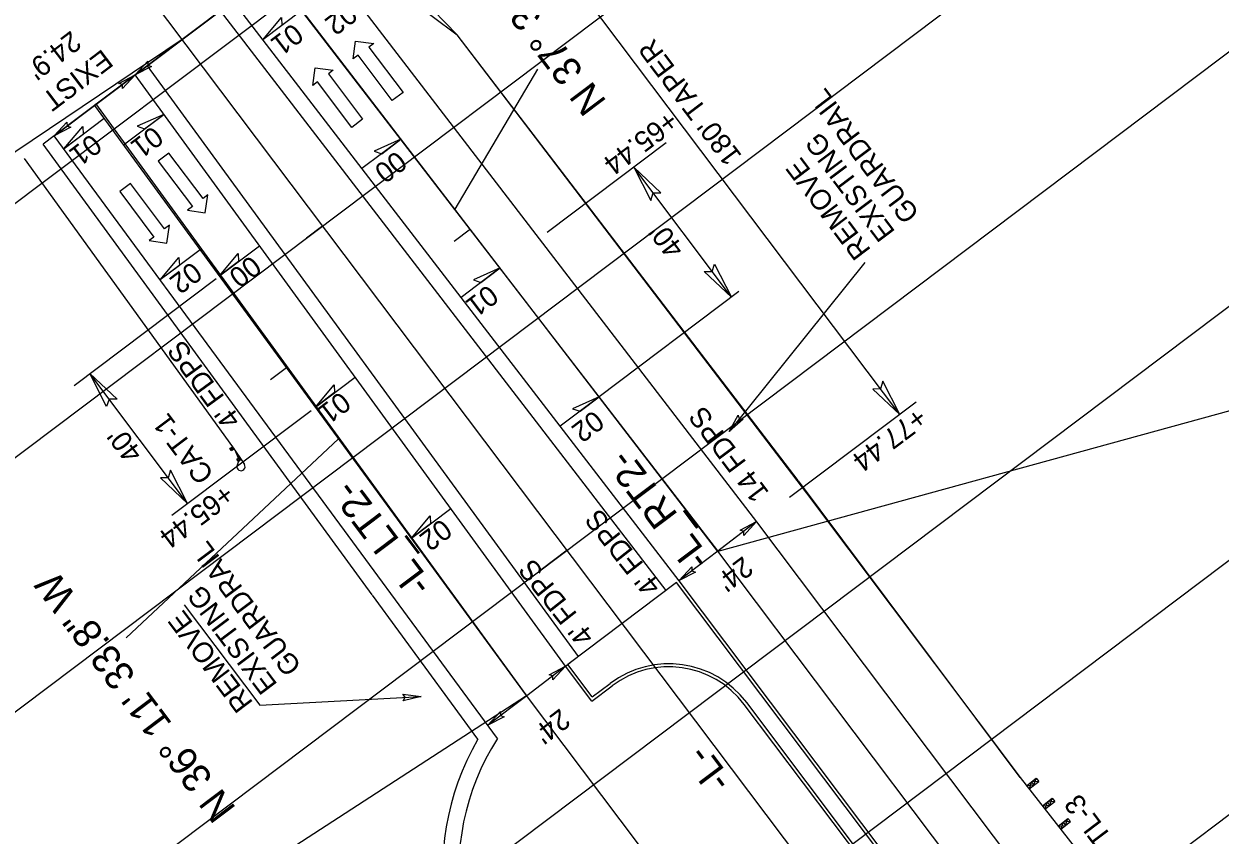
# Model space of a CAD drawing. Extents: x 1262309 to 1264352, y 775189 to 777755.
# Drawn here: x 1262668.6 to 1262963, y 777260.9 to 777460.6 of the extents above; entities that cross this region are included whole.
import ezdxf

# ---------------------------------------------------------------- set-up
doc = ezdxf.new("R2010")
doc.units = 0
for name, color, linetype in [('Default', 7, 'Continuous'), ('Prop Conc 5in Monolithic Keyed In Island', 7, 'Continuous'), ('Prop Dimension', 7, 'Continuous'), ('Prop Dimension Text', 7, 'Continuous'), ('Prop EOT', 7, 'Continuous'), ('Prop GRAU CAT1 Cell', 7, 'Continuous'), ('Prop Guardrail', 7, 'Continuous'), ('Prop Guardrail Anchor Unit CELL', 7, 'Continuous'), ('Prop Horizontal Alignment', 7, 'Continuous'), ('Prop Horizontal Alignment Station Label', 7, 'Continuous'), ('Prop Horizontal Alignment Tick Large', 7, 'Continuous'), ('Prop Horizontal Alignment Tick Small', 7, 'Continuous'), ('Prop Lane Arrow CELL', 7, 'Continuous'), ('Prop Lane Lines', 7, 'Continuous'), ('Prop Paved Shoulder', 7, 'Continuous'), ('Prop Superelevation  Arrow CELL', 7, 'Continuous'), ('Prop Superelevation Label', 7, 'Continuous'), ('Prop Terminator CELL', 7, 'Continuous'), ('Scratch_Level_3', 7, 'Continuous')]:
    doc.layers.add(name, color=color, linetype=linetype)

msp = doc.modelspace()

# ---------------------------------------------------------------- linework, layer by layer
at = {"layer": 'Default'}
for p, q in [((1262742.12, 777410.88), (1262742.12, 777410.88)), ((1262742.12, 777410.88), (1262742.12, 777410.88)), ((1262802.29, 777331), (1262802.29, 777331)), ((1262802.29, 777331), (1262802.29, 777331))]:
    msp.add_line(p, q, dxfattribs=at)
at = {"layer": 'Prop Conc 5in Monolithic Keyed In Island'}
for p, q in [((1262829.24, 777323.06), (1262802.48, 777302.91)), ((1262891.25, 777240.73), (1262829.24, 777323.06)), ((1262808.49, 777294.92), (1262802.48, 777302.91)), ((1262808.49, 777294.92), (1262812.89, 777298.23)), ((1262888.06, 777238.32), (1262846.5, 777293.5))]:
    msp.add_line(p, q, dxfattribs=at)
msp.add_arc((1262827.33, 777279.06), 24, 36.9874, 126.9874, dxfattribs=at)
at = {"layer": 'Prop Dimension'}
for p, q in [((1262842.76, 777393.34), (1262818.69, 777425.29)), ((1262680.93, 777371.6), (1262715.9, 777397.94)), ((1262844.57, 777394.7), (1262810.17, 777368.79)), ((1262708.83, 777342.54), (1262684.76, 777374.49)), ((1262705, 777339.65), (1262739.25, 777365.45))]:
    msp.add_line(p, q, dxfattribs=at)
for points in [[(1262699.99, 777450.12), (1262695.94, 777448.01), (1262699.06, 777451.38), (1262699.09, 777450.4)], [(1262691.93, 777445.92), (1262695.98, 777448.03), (1262692.87, 777444.65), (1262692.84, 777445.64)], [(1262680.1, 777435.13), (1262676.05, 777433.02), (1262679.16, 777436.4), (1262679.19, 777435.41)]]:
    msp.add_lwpolyline(points, close=True, dxfattribs=at)
at = {"layer": 'Prop Dimension Text'}
for p, q in [((1262884.16, 777364.43), (1262775.74, 777508.38)), ((1262720.06, 777466.17), (1262695.95, 777448.02)), ((1262695.94, 777448.01), (1262676.05, 777433.02)), ((1262695.94, 777448.01), (1262676.05, 777433.02)), ((1262826.65, 777431.28), (1262797.38, 777409.24)), ((1262888.21, 777367.48), (1262857, 777343.97)), ((1262848.94, 777338.05), (1262839.04, 777330.52)), ((1262848.94, 777338.05), (1262839.39, 777330.78)), ((1262839.39, 777330.78), (1262829.83, 777323.52)), ((1262708, 777317.57), (1262726.64, 777292.83)), ((1262801.88, 777302.46), (1262792.33, 777295.19)), ((1262792.33, 777295.19), (1262782.78, 777287.93))]:
    msp.add_line(p, q, dxfattribs=at)
for points in [[(1262825.34, 777419.03), (1262818.69, 777425.29), (1262822.86, 777417.1), (1262823.44, 777418.98)], [(1262838.58, 777401.46), (1262842.76, 777393.34), (1262836.03, 777399.6), (1262838, 777399.65)], [(1262688.94, 777366.37), (1262684.76, 777374.49), (1262691.49, 777368.22), (1262689.52, 777368.18)], [(1262877.51, 777370.68), (1262884.16, 777364.43), (1262879.99, 777372.62), (1262879.41, 777370.74)], [(1262702.18, 777348.8), (1262708.83, 777342.54), (1262704.66, 777350.73), (1262704.08, 777348.85)], [(1262844.89, 777335.94), (1262848.94, 777338.05), (1262845.82, 777334.67), (1262845.79, 777335.65)], [(1262844.89, 777335.94), (1262848.94, 777338.05), (1262845.82, 777334.67), (1262845.79, 777335.65)], [(1262833.89, 777325.62), (1262829.83, 777323.52), (1262832.95, 777326.89), (1262832.98, 777325.91)], [(1262797.83, 777300.35), (1262801.88, 777302.46), (1262798.76, 777299.08), (1262798.74, 777300.06)], [(1262786.83, 777290.03), (1262782.78, 777287.93), (1262785.89, 777291.3), (1262785.92, 777290.32)]]:
    msp.add_lwpolyline(points, close=True, dxfattribs=at)
for points in [[(1262875.6, 777401.82), (1262842.2, 777360.23)], [(1262726.64, 777292.83), (1262766.38, 777295.04)]]:
    msp.add_lwpolyline(points, dxfattribs=at)
at = {"layer": 'Prop EOT'}
for p, q in [((1262676.05, 777433.02), (1262739.39, 777480.73)), ((1262848.98, 777337.98), (1262739.39, 777480.73)), ((1262695.94, 777448.01), (1262720.06, 777466.17)), ((1262829.84, 777323.51), (1262720.06, 777466.17)), ((1262801.88, 777302.46), (1262695.94, 777448.01)), ((1262785.15, 777284.66), (1262676.05, 777433.02)), ((1262808.35, 777293.87), (1262801.88, 777302.46)), ((1262808.35, 777293.87), (1262813.34, 777297.63)), ((1262887.46, 777237.86), (1262845.9, 777293.05))]:
    msp.add_line(p, q, dxfattribs=at)
for points in [[(1262965.52, 777183.26), (1262848.98, 777337.98)], [(1262891.85, 777241.18), (1262829.84, 777323.51)]]:
    msp.add_lwpolyline(points, dxfattribs=at)
for centre, radius, start, end in [((1262827.33, 777279.06), 23.25, 36.9874, 126.9874), ((1262835.62, 777252.21), 60, 147.262, 230.9826)]:
    msp.add_arc(centre, radius, start, end, dxfattribs=at)
at = {"layer": 'Prop GRAU CAT1 Cell'}
for p, q in [((1262719.23, 777356.05), (1262719.9, 777356.5)), ((1262719.62, 777355.47), (1262719.23, 777356.05)), ((1262720.29, 777355.92), (1262719.23, 777356.05)), ((1262719.9, 777356.5), (1262719.62, 777355.47)), ((1262720.29, 777355.92), (1262719.62, 777355.47)), ((1262719.9, 777356.5), (1262721.88, 777353.56)), ((1262719.9, 777356.5), (1262720.29, 777355.92)), ((1262721.5, 777353.41), (1262720.77, 777355.21)), ((1262720.97, 777353.47), (1262721.64, 777353.92)), ((1262721.36, 777352.89), (1262720.97, 777353.47)), ((1262722.03, 777353.34), (1262720.97, 777353.47)), ((1262721.08, 777351.91), (1262721.44, 777352.95)), ((1262721.64, 777353.92), (1262721.36, 777352.89)), ((1262722.03, 777353.34), (1262721.36, 777352.89)), ((1262721.64, 777353.92), (1262722.03, 777353.34)), ((1262721.95, 777353.45), (1262721.88, 777353.56)), ((1262721.88, 777353.56), (1262722.84, 777352.14))]:
    msp.add_line(p, q, dxfattribs=at)
msp.add_ellipse((1262722.01, 777351.58), major_axis=(0.824, 0.555), ratio=0.995379, start_param=2.210226, end_param=6.283185, dxfattribs=at)
at = {"layer": 'Prop Guardrail'}
for p, q in [((1262775.22, 777457.9), (1262747.34, 777486.63)), ((1262859.18, 777348.14), (1262775.22, 777457.9)), ((1262668.63, 777427.42), (1262719.9, 777356.5)), ((1262913.85, 777275.05), (1262859.21, 777348.11))]:
    msp.add_line(p, q, dxfattribs=at)
at = {"layer": 'Prop Guardrail Anchor Unit CELL'}
for p, q in [((1262913.83, 777275.03), (1262942.69, 777238.26)), ((1262915.4, 777273.03), (1262917.76, 777274.88)), ((1262916.01, 777272.24), (1262918.37, 777274.1)), ((1262916.58, 777273.96), (1262916.01, 777272.24)), ((1262918.37, 777274.1), (1262916.58, 777273.96)), ((1262916.58, 777273.96), (1262917.19, 777273.17)), ((1262917.19, 777273.17), (1262917.76, 777274.88)), ((1262917.76, 777274.88), (1262918.37, 777274.1)), ((1262917.19, 777273.17), (1262915.4, 777273.03)), ((1262915.4, 777273.03), (1262916.01, 777272.24)), ((1262916.01, 777272.24), (1262917.19, 777273.17)), ((1262919.29, 777268.08), (1262921.69, 777269.96)), ((1262919.29, 777268.08), (1262921.11, 777268.23)), ((1262919.9, 777267.29), (1262922.31, 777269.17)), ((1262920.49, 777269.02), (1262919.9, 777267.29)), ((1262922.31, 777269.17), (1262920.49, 777269.02)), ((1262920.49, 777269.02), (1262921.11, 777268.23)), ((1262921.11, 777268.23), (1262921.69, 777269.96)), ((1262921.69, 777269.96), (1262922.31, 777269.17)), ((1262923.18, 777263.12), (1262925.57, 777265)), ((1262924.99, 777263.27), (1262925.57, 777265)), ((1262925.57, 777265), (1262926.19, 777264.21)), ((1262923.18, 777263.12), (1262924.99, 777263.27)), ((1262923.8, 777262.33), (1262926.19, 777264.21)), ((1262924.38, 777264.06), (1262923.8, 777262.33)), ((1262926.19, 777264.21), (1262924.38, 777264.06)), ((1262924.38, 777264.06), (1262924.99, 777263.27))]:
    msp.add_line(p, q, dxfattribs=at)
at = {"layer": 'Prop Horizontal Alignment'}
for p, q in [((1263127.22, 776899.61), (1262639.84, 777546.67)), ((1262839.42, 777330.73), (1262729.72, 777473.45)), ((1262839.42, 777330.73), (1262729.72, 777473.45)), ((1262792.29, 777295.24), (1262685.99, 777440.52)), ((1262792.29, 777295.24), (1262685.99, 777440.52)), ((1262792.29, 777295.24), (1262685.99, 777440.52)), ((1262792.29, 777295.24), (1262685.99, 777440.52))]:
    msp.add_line(p, q, dxfattribs=at)
at = {"layer": 'Prop Horizontal Alignment Station Label'}
for p, q in [((1262795.02, 777449.4), (1262774.64, 777414.98)), ((1262992.51, 777372.78), (1262839.42, 777330.73)), ((1262693.74, 777309.43), (1262746.03, 777358.47)), ((1262632.6, 777191.78), (1262792.29, 777295.24))]:
    msp.add_line(p, q, dxfattribs=at)
msp.add_lwpolyline([(1262707.56, 777456.76), (1262417.03, 777261.18), (1262308.75, 777404.89)], dxfattribs=at)
at = {"layer": 'Prop Horizontal Alignment Tick Large'}
msp.add_line((1262802.29, 777331), (1262795.9, 777326.19), dxfattribs=at)
at = {"layer": 'Prop Horizontal Alignment Tick Small'}
for p, q in [((1262742.12, 777410.88), (1262738.13, 777407.87)), ((1262778.48, 777410.02), (1262774.49, 777407.01)), ((1262733.24, 777375.94), (1262729.25, 777372.93))]:
    msp.add_line(p, q, dxfattribs=at)
at = {"layer": 'Prop Lane Arrow CELL'}
for p, q in [((1262749.63, 777451.99), (1262750.22, 777456.37)), ((1262750.22, 777456.37), (1262754.67, 777455.78)), ((1262754.67, 777455.78), (1262753.47, 777454.88)), ((1262753.47, 777454.88), (1262761.89, 777443.7)), ((1262750.83, 777452.89), (1262749.63, 777451.99)), ((1262759.26, 777441.71), (1262750.83, 777452.89)), ((1262739.67, 777445.39), (1262740.25, 777449.77)), ((1262740.25, 777449.77), (1262744.71, 777449.18)), ((1262744.71, 777449.18), (1262743.51, 777448.28)), ((1262743.51, 777448.28), (1262751.93, 777437.1)), ((1262740.87, 777446.3), (1262739.67, 777445.39)), ((1262749.29, 777435.11), (1262740.87, 777446.3)), ((1262761.89, 777443.7), (1262759.26, 777441.71)), ((1262751.93, 777437.1), (1262749.29, 777435.11)), ((1262704.24, 777428.76), (1262701.61, 777426.78)), ((1262701.61, 777426.78), (1262710.03, 777415.59)), ((1262712.67, 777417.58), (1262704.24, 777428.76)), ((1262694.79, 777421.29), (1262692.15, 777419.31)), ((1262703.21, 777410.11), (1262694.79, 777421.29)), ((1262692.15, 777419.31), (1262700.57, 777408.12)), ((1262713.87, 777418.48), (1262712.67, 777417.58)), ((1262713.21, 777414.04), (1262713.87, 777418.48)), ((1262710.03, 777415.59), (1262708.83, 777414.69)), ((1262708.83, 777414.69), (1262713.21, 777414.04)), ((1262704.41, 777411.01), (1262703.21, 777410.11)), ((1262703.75, 777406.57), (1262704.41, 777411.01)), ((1262700.57, 777408.12), (1262699.37, 777407.22)), ((1262699.37, 777407.22), (1262703.75, 777406.57))]:
    msp.add_line(p, q, dxfattribs=at)
at = {"layer": 'Prop Lane Lines'}
for p, q in [((1262839.35, 777330.83), (1262729.57, 777473.49)), ((1262792.18, 777295.39), (1262686.24, 777440.95)), ((1263348.11, 776655.37), (1262839.39, 777330.78))]:
    msp.add_line(p, q, dxfattribs=at)
msp.add_lwpolyline([(1263120.31, 776859.74), (1262792.29, 777295.24)], dxfattribs=at)
at = {"layer": 'Prop Paved Shoulder'}
for p, q in [((1262742.03, 777482.72), (1262775.22, 777457.9)), ((1262826.64, 777321.11), (1262716.94, 777463.83)), ((1262861.28, 777345.08), (1262775.22, 777457.9)), ((1262805.07, 777304.86), (1262698.97, 777450.29)), ((1262676.05, 777433.02), (1262673.3, 777430.96)), ((1262754.27, 777320.04), (1262673.3, 777430.96)), ((1262913.87, 777275.07), (1262861.28, 777345.08)), ((1262780.34, 777284.46), (1262754.42, 777319.94)), ((1262801.88, 777302.46), (1262802.94, 777303.26)), ((1262913.85, 777275.05), (1262943, 777237.86))]:
    msp.add_line(p, q, dxfattribs=at)
msp.add_arc((1262835.62, 777252.21), 64, 149.7341, 230.9826, dxfattribs=at)
at = {"layer": 'Prop Superelevation  Arrow CELL'}
for points in [[(1262727.37, 777456.66), (1262732, 777462.15), (1262732.09, 777460.21)], [(1262703, 777438.31), (1262696.45, 777435.37), (1262698.29, 777434.76)], [(1262678.42, 777429.8), (1262683.04, 777435.29), (1262683.13, 777433.35)], [(1262761.36, 777432.18), (1262754.8, 777429.25), (1262756.64, 777428.63)], [(1262702.11, 777397.57), (1262706.74, 777403.06), (1262706.83, 777401.12)], [(1262716.7, 777398.55), (1262721.33, 777404.04), (1262721.42, 777402.1)], [(1262785.79, 777400.51), (1262779.24, 777397.57), (1262781.08, 777396.96)], [(1262740.32, 777366.26), (1262744.95, 777371.75), (1262745.04, 777369.81)], [(1262810.17, 777368.79), (1262803.61, 777365.86), (1262805.46, 777365.24)], [(1262763.95, 777333.98), (1262768.58, 777339.47), (1262768.66, 777337.53)]]:
    msp.add_lwpolyline(points, close=True, dxfattribs=at)
at = {"layer": 'Prop Superelevation Label'}
for p, q in [((1262737.03, 777463.94), (1262727.37, 777456.66)), ((1262684.89, 777439.69), (1262676.05, 777433.02)), ((1262688.36, 777437.29), (1262678.45, 777429.83)), ((1262693.08, 777430.83), (1262703, 777438.31)), ((1262761.41, 777432.22), (1262751.77, 777424.96)), ((1262716.7, 777398.55), (1262726.55, 777405.96)), ((1262711.98, 777405), (1262702.15, 777397.6)), ((1262785.79, 777400.51), (1262776.17, 777393.26)), ((1262740.32, 777366.26), (1262750.09, 777373.61)), ((1262810.17, 777368.79), (1262800.56, 777361.56)), ((1262763.95, 777333.98), (1262773.63, 777341.27))]:
    msp.add_line(p, q, dxfattribs=at)
at = {"layer": 'Prop Terminator CELL'}
for points in [[(1262845.62, 777363.25), (1262842.2, 777360.23), (1262844.41, 777364.26), (1262844.67, 777363.31)], [(1262761.84, 777295.54), (1262766.38, 777295.04), (1262761.91, 777293.97), (1262762.44, 777294.8)]]:
    msp.add_lwpolyline(points, close=True, dxfattribs=at)
at = {"layer": 'Scratch_Level_3'}
for p, q in [((1262514.1, 777301.73), (1263009.2, 777674.65)), ((1262544.18, 777261.79), (1263039.29, 777634.71)), ((1262574.27, 777221.85), (1263069.37, 777594.77)), ((1262604.35, 777181.92), (1263099.45, 777554.83)), ((1262634.43, 777141.98), (1263129.53, 777514.89)), ((1262664.51, 777102.04), (1263159.61, 777474.95)), ((1262694.59, 777062.1), (1263189.7, 777435.02))]:
    msp.add_line(p, q, dxfattribs=at)

# ---------------------------------------------------------------- texts
at = {"layer": 'Prop Dimension'}
msp.add_text("180' TAPER", height=5, rotation=127.0213, dxfattribs=at).set_placement((1262845.47, 777428.1))
at = {"layer": 'Prop Dimension Text'}
for s, rotation, p in [("24.9'", 217.2584, (1262680.2, 777459.09)), ('GUARDRAIL', 126.9874, (1262889.21, 777413.91)), ('+65.44', 216.9874, (1262827.26, 777439.48)), ('EXISTING', 126.9874, (1262883.22, 777409.4)), ('REMOVE', 126.9874, (1262877.23, 777404.89)), ("40'", 127.0213, (1262831.32, 777405.24)), ("4' FDPS", 126.2273, (1262722.17, 777363.18)), ('14 FDPS', 126.9874, (1262852.17, 777345.19)), ('+77.44', 216.9874, (1262888.53, 777366.41)), ("40'", 126.9874, (1262697.99, 777354.89)), ('+65.44', 216.9874, (1262717.96, 777347.54)), ("4' FDPS", 128.3987, (1262825.56, 777322.22)), ('GUARDRAIL', 126.9874, (1262737.13, 777302.48)), ("24'", 217.2584, (1262845.61, 777329.73)), ("4' FDPS", 128.3987, (1262809.2, 777309.9)), ('EXISTING', 126.9874, (1262731.14, 777297.96)), ('REMOVE', 126.9874, (1262725.15, 777293.45)), ("24'", 217.2584, (1262800.58, 777292.23))]:
    msp.add_text(s, height=5, rotation=rotation, dxfattribs=at).set_placement(p)
at = {"layer": 'Prop Guardrail Anchor Unit CELL'}
for s, p in [('CAT-1', (1262715.56, 777349.69)), ('GREU TL-3', (1262949.33, 777243.5))]:
    msp.add_text(s, height=5, rotation=126.9874, dxfattribs=at).set_placement(p)
at = {"layer": 'Prop Horizontal Alignment Station Label'}
for s, rotation, p in [('N 37%%d 32\' 51.1" W', 127.0213, (1262812.18, 777441.46)), ('-L_RT2-', 126.9874, (1262837.89, 777328.9)), ('-L_LT2-', 126.9874, (1262769.37, 777322.68)), ('N 36%%d 11\' 33.8" W', 127.0213, (1262720.97, 777267.43)), ('-L-', 126.9874, (1262843.14, 777274.39))]:
    msp.add_text(s, height=7, rotation=rotation, dxfattribs=at).set_placement(p)
at = {"layer": 'Prop Superelevation Label'}
for s, p in [('02', (1262748.16, 777465.94)), ('01', (1262734.86, 777460.97)), ('EXIST', (1262687.94, 777454.56)), ('01', (1262685.25, 777433.74)), ('01', (1262700.37, 777435.66)), ('00', (1262760.34, 777429.54)), ('00', (1262724.52, 777403.78)), ('02', (1262709.94, 777402.27)), ('01', (1262782.87, 777396.61)), ('01', (1262746.53, 777370.28)), ('02', (1262808.9, 777365.69)), ('02', (1262771.45, 777338.98))]:
    msp.add_text(s, height=5, rotation=217.2584, dxfattribs=at).set_placement(p)

doc.saveas('drawing.dxf')
